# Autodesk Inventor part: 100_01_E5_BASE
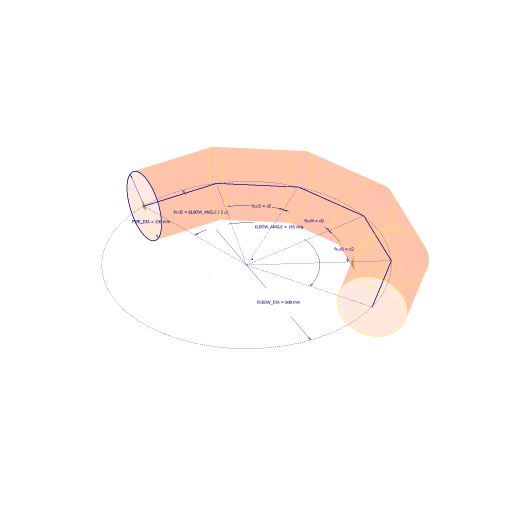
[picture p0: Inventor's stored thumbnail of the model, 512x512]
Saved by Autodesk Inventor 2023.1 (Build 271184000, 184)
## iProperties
Company: Fabian Stasiak CAD Consulting
Category: Autodesk® Inventor® Tutorial Series
Created: 2017-01
Part Number: 100_01_E5_BASE
Material: Stal
Document SubType Name: Modeling
Designer: F.Stasiak
Density: 7.85 g/cm^3
Appearance: Stal
Catalog Web Link: www.expertbooks.eu
Author: F.Stasiak
Subject: Sheet Metal Design. Basic and Advanced techniques
## Parameters: ELBOW_ANGLE = 165 deg, d2 = 33 deg, d3 = 33 deg, d4 = 33 deg, d5 = 33 deg, d7 = 0, d8 = 0
